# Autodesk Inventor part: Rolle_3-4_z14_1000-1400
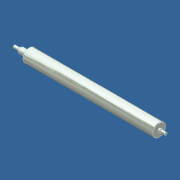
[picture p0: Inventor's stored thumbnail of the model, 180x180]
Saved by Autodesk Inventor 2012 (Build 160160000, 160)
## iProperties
Shininess: 64.0
Length Units: 11269
Angle Units: 11279
Time Units: 11290
Mass Units: 11283
Length Display Precision: 3
Angle Display Precision: 2
Compacted: True
Part Number: Rolle_3-4_z14_1000-1400
Document SubType Name: Modeling
Created: 2004-09
Material: Standard
Designer: Greiling
Manufacturer: Standard
Standards Organization: Custom
Density: 1 g/cm^3
Density: 0.0
Volumn: 0.0
Area: 0.0
PropertySet Name: Model Information
Control State: 0
Master: False
Checked Out: False
Author: Greiling
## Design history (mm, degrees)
sketch "Skizze1"
  geometry: L1 (0, 90.805)-(0, -6.985) reference; L2 (0, -6.985)-(0, 90.805) reference; L3 (5, 69.85)-(1395, 69.85); L4 (1400, 64.85)-(1400, 20); L5 (1400, 20)-(1415, 20); L6 (1415, 20)-(1415, 21); L7 (1421, 15)-(1468, 15); L8 (1470, 13)-(1470, 0); L9 (0, 32)-(-28.9, 32); L10 (-40, 32)-(-68.9, 32); L11 (-80, 32)-(-80, 20); L12 (-80, 20)-(-102, 20); L13 (-102, 20)-(-102, 21); L14 (-108, 15)-(-155, 15); L15 (-157, 13)-(-157, 0); L16 (-157, 0)-(1470, 0); L17 (1470, 13)-(1468, 15); L18 (-155, 15)-(-157, 13); L19 (0, 64.85)-(0, 32); L20 (0, 64.85)-(5, 69.85); L21 (1395, 69.85)-(1400, 64.85); L22 (0, 32)-(-80, 32); L23 (10, 0)-(10, 64.85); L24 (10, 64.85)-(1390, 64.85); L25 (1390, 64.85)-(1390, 0); A1 r 6 centre (1421, 21) between (1415, 21) and (1421, 15); A2 r 6 centre (-108, 21) between (-108, 15) and (-102, 21); 6 further points
  constraints: 46 end point, 17 point on line, 6 perpendicular, 5 parallel, 4 point on circle, 4 tangent, 2 centre point, 2 collinear, 1 equal radius
  dimensions: "d1" = 139.7 diameter of L3 L16; "d2" = 40 diameter of L5 L16; "d3" = 30 diameter of L7 L16; "d4" = 30 diameter of L14 L16; "d5" = 40 diameter of L12 L16; "d10" = 80 distance from line of point (0, 69.85) L11; "d11" = 55 distance of point (-102, 15) point (-157, 15); "d12" = 157 distance from line of L15 point (0, 69.85); "d14" = 64 diameter of L9 L16; "d15" = 64 diameter of L10 L16; "Rollenbreite" = 1400 distance of point (0, 69.85) point (1400, 69.85); "d17" = 70 distance between parallel lines of L4 L8; "d18" = 55 distance of point (1415, 15) point (1470, 15); "d19" = 2 distance of L8.start point (1470, 15); "d20" = 2 distance of L7.end point (1470, 15) (= d19); "d21" = 6 radius of A1; "d22" = 2 distance of L14.end point (-157, 15); "d23" = 2 distance of L15.start point (-157, 15) (= d22); "d32" = 5 distance of L19.start point (0, 69.85); "d33" = 5 distance of L3.start point (0, 69.85) (= d32); "d34" = 5 distance of L3.end point (1400, 69.85) (= d32); "d35" = 5 distance of L4.start point (1400, 69.85) (= d34); "d37" = 10 distance between parallel lines of L4 L25; "d38" = 5 distance between parallel lines of L3 L24; "d39" = 10 distance between parallel lines of L23 L1
revolve "Drehung1" sketch "Skizze1" stored, may be unused: angle "d36" = 90 deg
node "Volumenkörper1"
node "Volumenkörpern"
node "Oberflächenkörpern"
